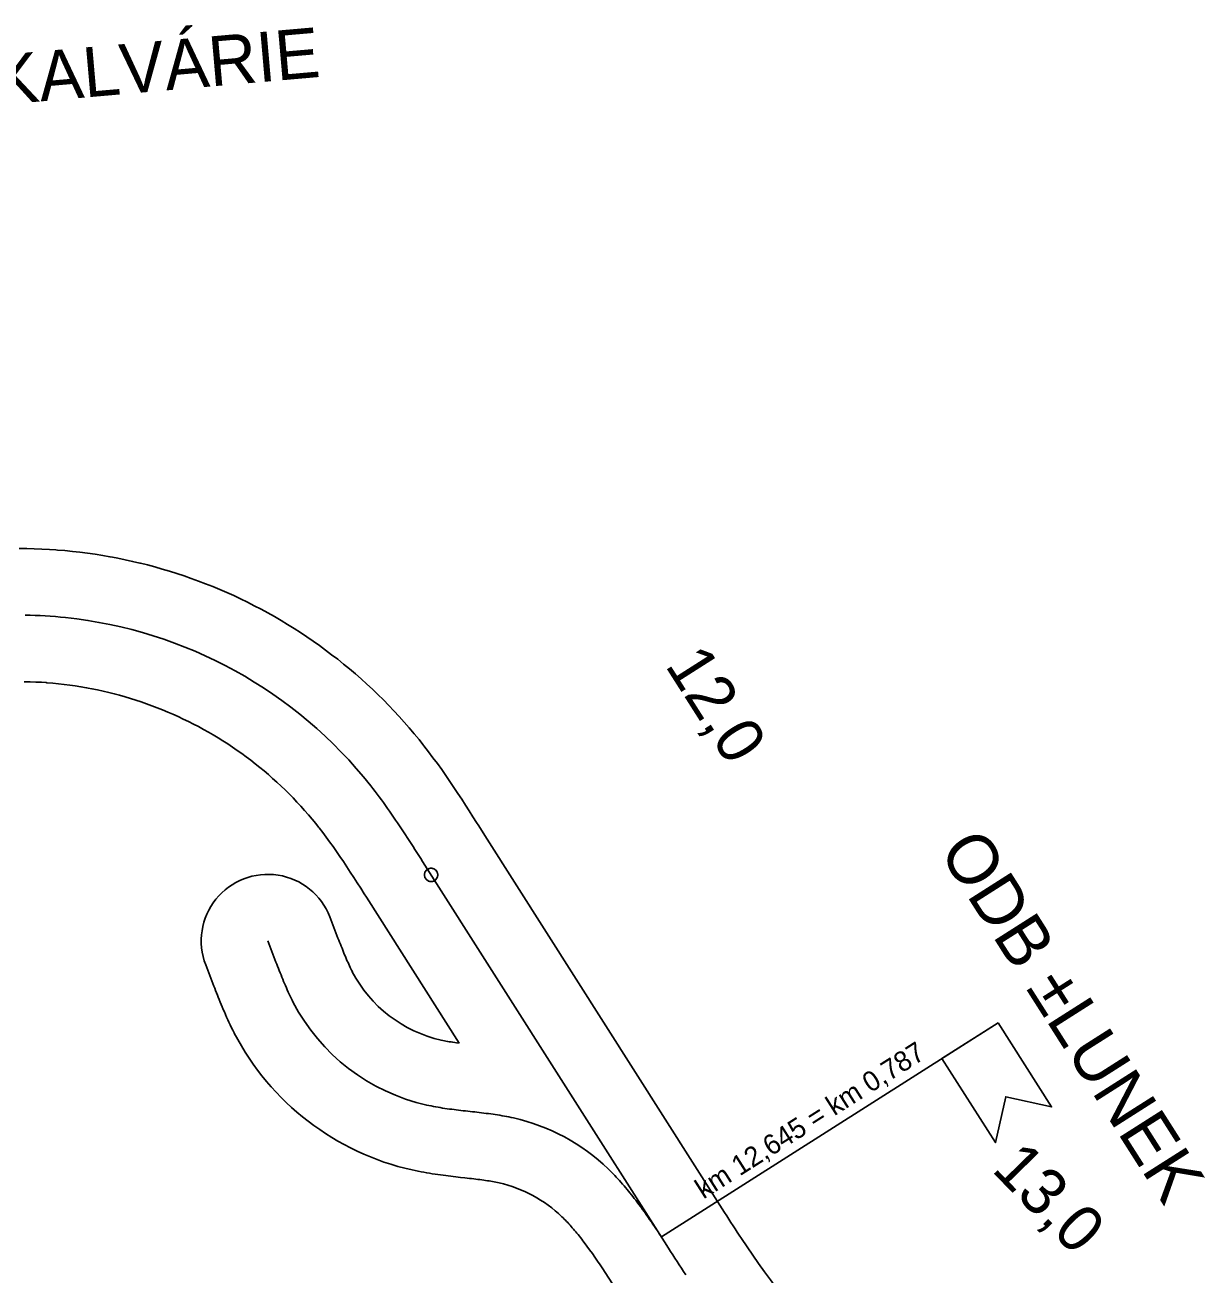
# Model space of a CAD drawing. Extents: x -670810 to -649614, y -1131928 to -1115069.
# Drawn here: x -668294 to -666520, y -1129446 to -1127567 of the extents above; entities that cross this region are included whole.
import ezdxf

# ---------------------------------------------------------------- set-up
doc = ezdxf.new("R2010")
doc.units = 0
for name, color, linetype in [('519 Var SK-4 Praporky stanic', 7, 'Continuous'), ('hranice_VRT_ZUR_Vysocina', 7, 'Continuous'), ('Situace - Osa koleje 2D', 7, 'Continuous'), ('Situace - Osa koleje tunel 2D', 7, 'Continuous'), ('Staničení - hlavní staničení + kolečka 1k', 7, 'Continuous')]:
    doc.layers.add(name, color=color, linetype=linetype)

# ---------------------------------------------------------------- blocks, each defined once
blk = doc.blocks.new('Sit10Kruh_178')
at = {"layer": 'Staničení - hlavní staničení + kolečka 1k'}
blk.add_lwpolyline([(10, 0), (9.98026, 0.6279), (9.92114, 1.25334), (9.82288, 1.87382), (9.68584, 2.4869), (9.51056, 3.09016), (9.29776, 3.68124), (9.04828, 4.2578), (8.76306, 4.81754), (8.44328, 5.35826), (8.09016, 5.87786), (7.70514, 6.37424), (7.28968, 6.84548), (6.84548, 7.28968), (6.37424, 7.70514), (5.87786, 8.09016), (5.35826, 8.44328), (4.81754, 8.76306), (4.2578, 9.04828), (3.68124, 9.29776), (3.09016, 9.51056), (2.4869, 9.68584), (1.87382, 9.82288), (1.25334, 9.92114), (0.6279, 9.98026), (0, 10), (-0.6279, 9.98026), (-1.25334, 9.92114), (-1.87382, 9.82288), (-2.4869, 9.68584), (-3.09016, 9.51056), (-3.68124, 9.29776), (-4.2578, 9.04828), (-4.81754, 8.76306), (-5.35826, 8.44328), (-5.87786, 8.09016), (-6.37424, 7.70514), (-6.84548, 7.28968), (-7.28968, 6.84548), (-7.70514, 6.37424), (-8.09016, 5.87786), (-8.44328, 5.35826), (-8.76306, 4.81754), (-9.04828, 4.2578), (-9.29776, 3.68124), (-9.51056, 3.09016), (-9.68584, 2.4869), (-9.82288, 1.87382), (-9.92114, 1.25334), (-9.98026, 0.6279), (-10, 0), (-9.98026, -0.6279), (-9.92114, -1.25334), (-9.82288, -1.87382), (-9.68584, -2.4869), (-9.51056, -3.09016), (-9.29776, -3.68124), (-9.04828, -4.2578), (-8.76306, -4.81754), (-8.44328, -5.35826), (-8.09016, -5.87786), (-7.70514, -6.37424), (-7.28968, -6.84548), (-6.84548, -7.28968), (-6.37424, -7.70514), (-5.87786, -8.09016), (-5.35826, -8.44328), (-4.81754, -8.76306), (-4.2578, -9.04828), (-3.68124, -9.29776), (-3.09016, -9.51056), (-2.4869, -9.68584), (-1.87382, -9.82288), (-1.25334, -9.92114), (-0.6279, -9.98026), (0, -10), (0.6279, -9.98026), (1.25334, -9.92114), (1.87382, -9.82288), (2.4869, -9.68584), (3.09016, -9.51056), (3.68124, -9.29776), (4.2578, -9.04828), (4.81754, -8.76306), (5.35826, -8.44328), (5.87786, -8.09016), (6.37424, -7.70514), (6.84548, -7.28968), (7.28968, -6.84548), (7.70514, -6.37424), (8.09016, -5.87786), (8.44328, -5.35826), (8.76306, -4.81754), (9.04828, -4.2578), (9.29776, -3.68124), (9.51056, -3.09016), (9.68584, -2.4869), (9.82288, -1.87382), (9.92114, -1.25334)], close=True, dxfattribs=at)
blk.add_circle((0, 0), 10, dxfattribs=at)
blk = doc.blocks.new('_U499')
at = {"layer": '519 Var SK-4 Praporky stanic'}
blk.add_line((-389.8, -306.8), (116.3, 15.1), dxfattribs=at)
blk.add_lwpolyline([(116.3, 15.1), (196.8, -111.4), (127.8, -96.1), (112.5, -165.1), (32, -38.5)], close=True, dxfattribs=at)
for s, height, rotation, p in [('ODB ±LUNEK', 75, 302.4607, (26.1, 273.3)), ('km 12,645 = km 0,787', 30, 32.4607, (-326.6, -250.7))]:
    blk.add_text(s, height=height, rotation=rotation, dxfattribs=at).set_placement(p)
blk = doc.blocks.new('_U709')
at = {"layer": '519 Var SK-4 Praporky stanic'}
blk.add_line((73.8, -456.3), (21.4, 141.2), dxfattribs=at)
blk.add_lwpolyline([(12.7, 240.8), (162.1, 253.9), (116.7, 199.7), (170.8, 154.3), (21.4, 141.2)], close=True, dxfattribs=at)
for s, height, rotation, p in [('ODB JIHLAVA-KALVÁRIE', 75, 5.0106, (-467.5, 261.5)), ('km 11,054', 30, 95.0106, (56.9, -417.8))]:
    blk.add_text(s, height=height, rotation=rotation, dxfattribs=at).set_placement(p)

msp = doc.modelspace()

# ---------------------------------------------------------------- linework, layer by layer
at = {"layer": 'hranice_VRT_ZUR_Vysocina'}
for points in [[(-668302.4, -1128354.1), (-668292.6, -1128354.2), (-668290.9, -1128354.2), (-668279.8, -1128354.5), (-668268.3, -1128354.9), (-668256.9, -1128355.5), (-668247.6, -1128356.1), (-668245.1, -1128356.3), (-668234, -1128357.2), (-668222.5, -1128358.4), (-668211.1, -1128359.6), (-668199.7, -1128361.1), (-668188.4, -1128362.7), (-668177, -1128364.5), (-668166, -1128366.4), (-668162.2, -1128367.1), (-668154.3, -1128368.6), (-668143.2, -1128370.9), (-668132, -1128373.4), (-668121.1, -1128375.9), (-668120, -1128376.2), (-668109.6, -1128378.8), (-668098.6, -1128381.7), (-668087.5, -1128384.9), (-668076.5, -1128388.1), (-668065.6, -1128391.6), (-668054.7, -1128395.2), (-668043.8, -1128399), (-668033, -1128402.9), (-668022.3, -1128407), (-668011.6, -1128411.2), (-668001, -1128415.6), (-667990.5, -1128420.2), (-667980, -1128424.9), (-667969.6, -1128429.8), (-667959.3, -1128434.8), (-667949.1, -1128440), (-667938.9, -1128445.3), (-667928.8, -1128450.8), (-667918.8, -1128456.4), (-667908.9, -1128462.2), (-667899, -1128468.1), (-667889.3, -1128474.2), (-667879.6, -1128480.4), (-667870.1, -1128486.8), (-667860.6, -1128493.3), (-667851.2, -1128499.9), (-667842, -1128506.7), (-667832.8, -1128513.6), (-667823.7, -1128520.6), (-667814.8, -1128527.8), (-667805.9, -1128535.1), (-667797.2, -1128542.6), (-667788.5, -1128550.1), (-667780, -1128557.8), (-667771.6, -1128565.6), (-667763.3, -1128573.6), (-667755.1, -1128581.7), (-667747.1, -1128589.8), (-667739.2, -1128598.1), (-667731.4, -1128606.6), (-667723.7, -1128615.1), (-667716.1, -1128623.8), (-667708.7, -1128632.5), (-667701.5, -1128641.3), (-667695.8, -1128648.4), (-667694.1, -1128650.6), (-667687.3, -1128659.4), (-667680.5, -1128668.4), (-667673.9, -1128677.4), (-667667.4, -1128686.4), (-667661.1, -1128695.4), (-667655, -1128704.4), (-667649, -1128713.3), (-667643.1, -1128722.2), (-667637.3, -1128731), (-667631.6, -1128739.8), (-667626, -1128748.4), (-667620.5, -1128757.1), (-667615, -1128765.6), (-667611.8, -1128770.7), (-667602.4, -1128785.5)], [(-668294.8, -1128554.2), (-668286, -1128554.4), (-668277.5, -1128554.7), (-668268.9, -1128555.1), (-668261.7, -1128555.6), (-668260.8, -1128555.7), (-668252, -1128556.4), (-668243.5, -1128557.3), (-668235, -1128558.2), (-668226.6, -1128559.3), (-668218.1, -1128560.5), (-668209.7, -1128561.8), (-668201.1, -1128563.3), (-668199, -1128563.7), (-668193.1, -1128564.8), (-668184.6, -1128566.6), (-668176.3, -1128568.4), (-668167.8, -1128570.4), (-668159.7, -1128572.4), (-668151.5, -1128574.6), (-668143.3, -1128576.9), (-668135.1, -1128579.4), (-668127, -1128581.9), (-668118.9, -1128584.6), (-668110.9, -1128587.4), (-668102.9, -1128590.3), (-668094.9, -1128593.3), (-668087, -1128596.5), (-668079.1, -1128599.8), (-668071.3, -1128603.2), (-668063.6, -1128606.7), (-668055.8, -1128610.3), (-668048.2, -1128614), (-668040.6, -1128617.8), (-668033, -1128621.8), (-668025.6, -1128625.9), (-668018.1, -1128630), (-668010.8, -1128634.3), (-668003.5, -1128638.7), (-667996.2, -1128643.2), (-667989.1, -1128647.8), (-667982, -1128652.5), (-667975, -1128657.4), (-667968, -1128662.3), (-667961.1, -1128667.3), (-667954.3, -1128672.4), (-667947.6, -1128677.7), (-667940.9, -1128683), (-667934.4, -1128688.4), (-667927.9, -1128693.9), (-667921.5, -1128699.5), (-667915.2, -1128705.2), (-667908.9, -1128711.1), (-667902.8, -1128716.9), (-667896.7, -1128722.9), (-667890.7, -1128729), (-667884.9, -1128735.2), (-667879.1, -1128741.4), (-667873.4, -1128747.7), (-667867.8, -1128754.2), (-667862.3, -1128760.7), (-667856.8, -1128767.3), (-667852.4, -1128772.8), (-667851.7, -1128773.7), (-667846.3, -1128780.7), (-667841, -1128787.7), (-667835.8, -1128794.8), (-667830.6, -1128802), (-667825.5, -1128809.4), (-667820.3, -1128816.9), (-667815.1, -1128824.6), (-667810, -1128832.4), (-667804.8, -1128840.3), (-667799.6, -1128848.3), (-667794.3, -1128856.4), (-667789.1, -1128864.7), (-667783.8, -1128873), (-667780.5, -1128878), (-667640.9, -1129097.6)], [(-667602.4, -1128785.5), (-667242.1, -1129351.9), (-667238.9, -1129356.9), (-667235.7, -1129361.9), (-667232.6, -1129366.9), (-667229.4, -1129371.8), (-667226.3, -1129376.6), (-667223.2, -1129381.4), (-667220.1, -1129386.2), (-667216.9, -1129391)], [(-667835.6, -1128907.7), (-667823.3, -1128939.5), (-667822, -1128942.7), (-667820.8, -1128945.8), (-667819.6, -1128948.9), (-667818.4, -1128951.9), (-667817.2, -1128954.9), (-667816.1, -1128957.8), (-667814.9, -1128960.7), (-667813.8, -1128963.5), (-667812.7, -1128966.2), (-667811.5, -1128968.9), (-667810.4, -1128971.5), (-667809.3, -1128974), (-667808.2, -1128976.5), (-667807.1, -1128978.9), (-667806, -1128981.3), (-667805, -1128983.6), (-667803.9, -1128985.8), (-667802.8, -1128987.9), (-667801.5, -1128990.5), (-667801.7, -1128990)], [(-668022.1, -1128979.9), (-668009.8, -1129011.7), (-668008.5, -1129015), (-668007.2, -1129018.3), (-668005.9, -1129021.7), (-668004.5, -1129025.1), (-668003.2, -1129028.6), (-668001.8, -1129032.1), (-668000.3, -1129035.7), (-667998.8, -1129039.4), (-667997.3, -1129043), (-667995.7, -1129046.8), (-667994.1, -1129050.6), (-667992.5, -1129054.4), (-667990.8, -1129058.3), (-667989, -1129062.2), (-667987.2, -1129066.1), (-667985.3, -1129070.1), (-667983.3, -1129074.2), (-667981.3, -1129078.2), (-667979.3, -1129082), (-667979.2, -1129082.3)], [(-667668.1, -1129092.9), (-667668.6, -1129092.8), (-667665.8, -1129093.4), (-667663.4, -1129093.9), (-667661, -1129094.4), (-667658.5, -1129094.8), (-667656, -1129095.3), (-667653.3, -1129095.7), (-667650.7, -1129096.2), (-667647.9, -1129096.6), (-667645.1, -1129097), (-667640.9, -1129097.6)], [(-667711.9, -1129288.1), (-667711.6, -1129288.1), (-667707.4, -1129289), (-667702.9, -1129290), (-667698.5, -1129290.8), (-667694.2, -1129291.6), (-667689.9, -1129292.4), (-667685.7, -1129293.1), (-667681.5, -1129293.8), (-667677.4, -1129294.4), (-667673.3, -1129295), (-667669.3, -1129295.6), (-667665.3, -1129296.1), (-667661.4, -1129296.6), (-667657.6, -1129297.1), (-667653.8, -1129297.5), (-667650.1, -1129298), (-667646.4, -1129298.4), (-667642.8, -1129298.8), (-667639.3, -1129299.2), (-667632.4, -1129299.9), (-667629, -1129300.3), (-667625.7, -1129300.7), (-667622.5, -1129301.1), (-667619.3, -1129301.4), (-667616.2, -1129301.8), (-667613.1, -1129302.2), (-667610.1, -1129302.6), (-667607.2, -1129303), (-667604.3, -1129303.4), (-667601.5, -1129303.8), (-667598.8, -1129304.2), (-667596.1, -1129304.6), (-667593.5, -1129305.1), (-667590.9, -1129305.5), (-667588.5, -1129306), (-667586, -1129306.5), (-667583.7, -1129306.9), (-667581.1, -1129307.5)], [(-667486.6, -1129358.4), (-667484.7, -1129360.2), (-667483.1, -1129361.9), (-667481.4, -1129363.6), (-667479.7, -1129365.3), (-667478, -1129367.1), (-667476.3, -1129369), (-667474.5, -1129370.9), (-667472.8, -1129372.8), (-667471.1, -1129374.8), (-667469.3, -1129376.8), (-667467.6, -1129378.9), (-667465.8, -1129381), (-667464.1, -1129383.1), (-667462.3, -1129385.3), (-667460.5, -1129387.5), (-667458.7, -1129389.8), (-667456.9, -1129392.1), (-667455.1, -1129394.5), (-667453.2, -1129396.9)], [(-667421.6, -1129442.4), (-667410.8, -1129459.2), (-667407.6, -1129464.3), (-667404.3, -1129469.4), (-667401.1, -1129474.6), (-667397.7, -1129479.8), (-667394.4, -1129485), (-667390.9, -1129490.3), (-667387.5, -1129495.6), (-667384.1, -1129500.9), (-667384, -1129500.9)]]:
    msp.add_lwpolyline(points, dxfattribs=at)
for centre, radius, start, end in [((-667928.8, -1128943.8), 100, 21.1699, 201.1699), ((-667624.3, -1128897.8), 200, 207.4724, 257.3521), ((-667624.3, -1128897.8), 400, 207.4724, 257.3521), ((-667625.2, -1129502.6), 200, 46.1432, 77.2789), ((-666047.9, -1128620.7), 1400, 213.3813, 233.3002), ((-667978.5, -1129796.6), 660, 32.4606, 37.2693)]:
    msp.add_arc(centre, radius, start, end, dxfattribs=at)
at = {"layer": 'Situace - Osa koleje 2D'}
for p, q in [((-667928.8, -1128943.8), (-667916.5, -1128975.6)), ((-667477.4, -1129168.4), (-667332.4, -1129396.2))]:
    msp.add_line(p, q, dxfattribs=at)
for points in [[(-667916.5, -1128975.6), (-667915.3, -1128978.8), (-667914, -1128982), (-667912.7, -1128985.3), (-667911.5, -1128988.5), (-667910.2, -1128991.7), (-667908.9, -1128995), (-667907.6, -1128998.2), (-667906.3, -1129001.4), (-667905, -1129004.6), (-667903.6, -1129007.8), (-667902.3, -1129011), (-667900.9, -1129014.2), (-667899.5, -1129017.4), (-667898.1, -1129020.6), (-667896.6, -1129023.7), (-667895.1, -1129026.8), (-667893.6, -1129030), (-667892, -1129033.1), (-667890.5, -1129036.2)], [(-667690, -1129190.5), (-667686.6, -1129191.2), (-667683.2, -1129191.9), (-667679.8, -1129192.6), (-667676.4, -1129193.2), (-667672.9, -1129193.8), (-667669.5, -1129194.4), (-667666.1, -1129195), (-667662.6, -1129195.5), (-667659.2, -1129196), (-667655.8, -1129196.5), (-667652.3, -1129196.9), (-667648.9, -1129197.4), (-667645.4, -1129197.8), (-667642, -1129198.2), (-667638.5, -1129198.6), (-667635.1, -1129199), (-667631.6, -1129199.4), (-667628.2, -1129199.8), (-667624.7, -1129200.2)], [(-667624.7, -1129200.2), (-667621.3, -1129200.6), (-667617.8, -1129200.9), (-667614.4, -1129201.3), (-667610.9, -1129201.7), (-667607.5, -1129202.1), (-667604, -1129202.6), (-667600.6, -1129203), (-667597.1, -1129203.4), (-667593.7, -1129203.9), (-667590.2, -1129204.4), (-667586.8, -1129204.9), (-667583.4, -1129205.4), (-667579.9, -1129205.9), (-667576.5, -1129206.5), (-667573.1, -1129207.1), (-667569.7, -1129207.8), (-667566.3, -1129208.4), (-667562.9, -1129209.1), (-667559.5, -1129209.9)], [(-667417, -1129286.5), (-667414.5, -1129289), (-667412.1, -1129291.4), (-667409.6, -1129293.9), (-667407.2, -1129296.4), (-667404.9, -1129298.9), (-667402.5, -1129301.5), (-667400.2, -1129304), (-667397.9, -1129306.6), (-667395.6, -1129309.3), (-667393.3, -1129311.9), (-667391.1, -1129314.5), (-667388.8, -1129317.2), (-667386.6, -1129319.9), (-667384.4, -1129322.6), (-667382.3, -1129325.3), (-667380.1, -1129328), (-667378, -1129330.8), (-667375.8, -1129333.5), (-667373.7, -1129336.3)]]:
    msp.add_lwpolyline(points, dxfattribs=at)
for centre, radius, start, end in [((-668303.7, -1129129.1), 675, 83.9863, 89.1537), ((-667624.3, -1128897.8), 300, 207.4724, 257.3521), ((-667625.2, -1129502.6), 300, 46.0695, 77.3521), ((-667978.5, -1129796.6), 760, 34.5048, 37.2791), ((-667978.5, -1129796.6), 760, 32.4607, 34.5048)]:
    msp.add_arc(centre, radius, start, end, dxfattribs=at)
at = {"layer": 'Situace - Osa koleje tunel 2D'}
for p, q in [((-667696.2, -1128824.4), (-667477.4, -1129168.4)), ((-667332.4, -1129396.2), (-667326.5, -1129405.6))]:
    msp.add_line(p, q, dxfattribs=at)
for points in [[(-667774.1, -1128710.6), (-667770.9, -1128714.8), (-667767.6, -1128719), (-667764.4, -1128723.2), (-667761.2, -1128727.4), (-667758.1, -1128731.7), (-667754.9, -1128736), (-667751.8, -1128740.3), (-667748.8, -1128744.6), (-667745.7, -1128749), (-667742.7, -1128753.3), (-667739.7, -1128757.7), (-667736.7, -1128762.1), (-667733.7, -1128766.5), (-667730.7, -1128770.9), (-667727.8, -1128775.3), (-667724.9, -1128779.7), (-667722, -1128784.2), (-667719.1, -1128788.6), (-667716.2, -1128793.1), (-667713.3, -1128797.5), (-667710.4, -1128802), (-667707.6, -1128806.5), (-667704.7, -1128810.9), (-667701.9, -1128815.4), (-667699, -1128819.9), (-667696.2, -1128824.4)], [(-667326.5, -1129405.6), (-667323.3, -1129410.6), (-667320, -1129415.7), (-667316.8, -1129420.7), (-667313.6, -1129425.8), (-667310.3, -1129430.8), (-667307.1, -1129435.9), (-667303.8, -1129440.9), (-667300.5, -1129445.9)]]:
    msp.add_lwpolyline(points, dxfattribs=at)
msp.add_arc((-668303.7, -1129129.1), 675, 38.3176, 83.9863, dxfattribs=at)

# ---------------------------------------------------------------- block references
at = {"layer": '519 Var SK-4 Praporky stanic'}
for name, p in [('_U709', (-668552.2, -1128009.3)), ('_U499', (-666947.4, -1129081.9))]:
    msp.add_blockref(name, p, dxfattribs=at)
at = {"layer": 'Staničení - hlavní staničení + kolečka 1k', "rotation": -57.539318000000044}
msp.add_blockref('Sit10Kruh_178', (-667683.3, -1128844.6), dxfattribs=at)

# ---------------------------------------------------------------- texts
at = {"layer": 'Staničení - hlavní staničení + kolečka 1k'}
for s, rotation, p in [('12,0', 302.4607, (-667332.6, -1128529.5)), ('13,0', 314.3465, (-666842.3, -1129288.6))]:
    msp.add_text(s, height=70, rotation=rotation, dxfattribs=at).set_placement(p)

doc.saveas('drawing.dxf')
